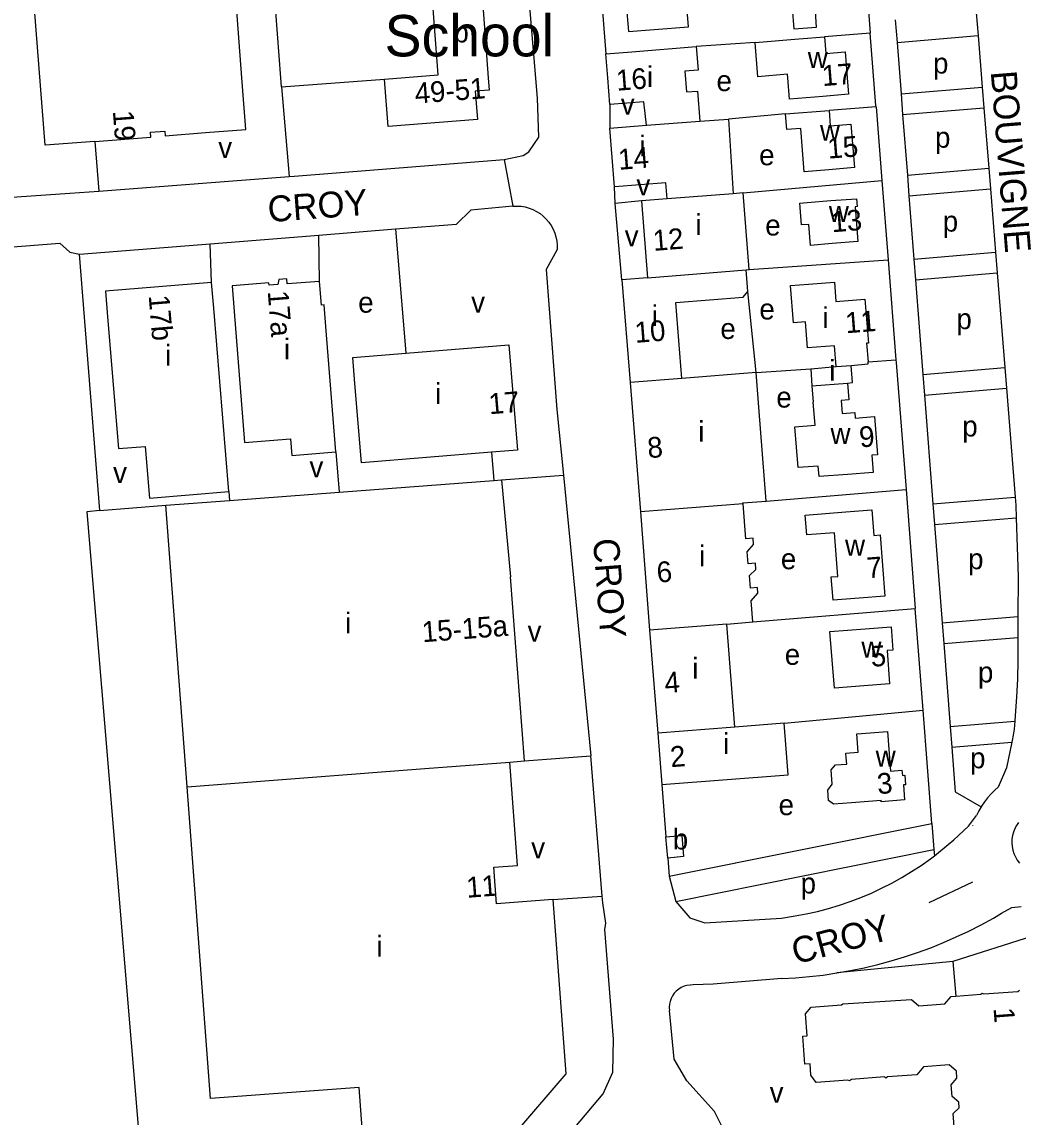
# Model space of a CAD drawing. Extents: x 157794 to 159375, y 380877 to 382306.
# Drawn here: x 158040.7 to 158233.2, y 381049.1 to 381260.8 of the extents above; entities that cross this region are included whole.
import ezdxf

# ---------------------------------------------------------------- set-up
doc = ezdxf.new("R2010")
doc.units = 0
for name, color, linetype in [('BLT_Basislijn', 7, 'Continuous'), ('BLT_Bebouwing', 7, 'Continuous'), ('BLT_Bebouwing_beschrifting', 7, 'Continuous'), ('BLT_Centroide', 7, 'Continuous'), ('BLT_Huisnummer', 7, 'Continuous'), ('BLT_Huisnummer_reeks', 7, 'Continuous'), ('BLT_Onderverdeling_panden', 7, 'Continuous'), ('BLT_Straatnaam', 7, 'Continuous'), ('BLT_Vlakafsluiter', 7, 'Continuous')]:
    doc.layers.add(name, color=color, linetype=linetype)

msp = doc.modelspace()

# ---------------------------------------------------------------- linework, layer by layer
at = {"layer": 'BLT_Basislijn'}
for p, q in [((158203.06, 381278.59), (158204.63, 381258.58)), ((158209.46, 381261.2), (158209.8, 381256.81)), ((158225.1, 381262.52), (158225.45, 381258.13)), ((158182.38, 381256.8), (158170.99, 381256.05)), ((158204.63, 381258.58), (158195.78, 381257.9)), ((158209.8, 381256.81), (158225.45, 381258.13)), ((158209.8, 381256.81), (158210.57, 381246.86)), ((158225.45, 381258.13), (158226.25, 381248.18)), ((158090.89, 381248.22), (158092.33, 381230.92)), ((158210.57, 381246.86), (158226.25, 381248.18)), ((158226.25, 381248.18), (158226.57, 381244.2)), ((158210.57, 381246.86), (158210.88, 381242.87)), ((158154.32, 381244.8), (158154.33, 381240.28)), ((158205.73, 381244.37), (158196.68, 381243.69)), ((158205.73, 381244.37), (158206.87, 381230.12)), ((158210.88, 381242.87), (158226.57, 381244.2)), ((158226.57, 381244.2), (158227.51, 381232.49)), ((158188.24, 381243.01), (158177.2, 381241.97)), ((158210.88, 381242.87), (158211.79, 381231.17)), ((158054.79, 381237.69), (158055.55, 381228.07)), ((158211.79, 381231.17), (158227.51, 381232.49)), ((158211.79, 381231.17), (158212.1, 381227.18)), ((158227.51, 381232.49), (158227.83, 381228.5)), ((158180.08, 381227.74), (158206.87, 381230.12)), ((158206.87, 381230.12), (158208.07, 381214.79)), ((158033.61, 381226.55), (158050, 381227.68)), ((158050, 381227.68), (158055.55, 381228.07)), ((158155.35, 381225.66), (158155.23, 381228.89)), ((158212.1, 381227.18), (158227.83, 381228.5)), ((158212.1, 381227.18), (158213.05, 381214.94)), ((158227.83, 381228.5), (158228.81, 381216.27)), ((158135.57, 381225.18), (158127.42, 381224.43)), ((158160.4, 381226.2), (158155.35, 381225.66)), ((158156.65, 381210.97), (158155.35, 381225.66)), ((158112.92, 381220.77), (158114.91, 381196.74)), ((158077.08, 381217.89), (158098.07, 381219.58)), ((158098.23, 381210.64), (158098.07, 381219.58)), ((158077.37, 381210.43), (158077.08, 381217.89)), ((158050, 381216.26), (158051.87, 381215.87)), ((158055.79, 381166.34), (158051.87, 381215.87)), ((158181.24, 381212.95), (158208.07, 381214.79)), ((158208.07, 381214.79), (158209.57, 381195.5)), ((158213.05, 381214.94), (158228.81, 381216.27)), ((158213.05, 381214.94), (158213.36, 381210.95)), ((158228.81, 381216.27), (158229.13, 381212.28)), ((158213.36, 381210.95), (158229.13, 381212.28)), ((158229.13, 381212.28), (158230.6, 381194)), ((158213.36, 381210.95), (158214.78, 381192.66)), ((158182.56, 381193.02), (158180.97, 381208.68)), ((158204.19, 381195.06), (158209.57, 381195.5)), ((158182.56, 381193.02), (158193.11, 381193.77)), ((158214.78, 381192.66), (158230.6, 381194)), ((158230.6, 381194), (158230.92, 381190.01)), ((158214.78, 381192.66), (158215.09, 381188.67)), ((158215.09, 381188.67), (158230.92, 381190.01)), ((158230.92, 381190.01), (158232.61, 381168.96)), ((158215.09, 381188.67), (158216.73, 381167.62)), ((158144.09, 381185.9), (158145.33, 381173.21)), ((158101.36, 381177.67), (158102.03, 381169.92)), ((158131.46, 381177.65), (158131.91, 381172.18)), ((158133.4, 381172.29), (158145.33, 381173.21)), ((158145.33, 381173.21), (158150.66, 381118.94)), ((158080.69, 381170), (158080.82, 381168.32)), ((158184.5, 381168.16), (158211.54, 381170.43)), ((158211.54, 381170.43), (158213.3, 381147.4)), ((158216.73, 381167.62), (158232.61, 381168.96)), ((158216.73, 381167.62), (158217.04, 381163.63)), ((158055.79, 381166.34), (158068.52, 381167.4)), ((158217.04, 381163.63), (158232.81, 381164.96)), ((158217.04, 381163.63), (158218.51, 381144.62)), ((158181.95, 381144.82), (158213.3, 381147.4)), ((158214.81, 381127.79), (158213.3, 381147.4)), ((158218.51, 381144.62), (158233.16, 381145.85)), ((158218.51, 381144.62), (158218.82, 381140.63)), ((158233.16, 381145.85), (158233.16, 381141.84)), ((158218.82, 381140.63), (158233.16, 381141.84)), ((158218.82, 381140.63), (158220.07, 381124.59)), ((158233.16, 381141.84), (158233.16, 381140.95)), ((158187.99, 381125.25), (158214.81, 381127.79)), ((158220.07, 381124.59), (158232.54, 381125.65)), ((158232.54, 381125.65), (158232.4, 381124.07)), ((158220.07, 381124.59), (158220.38, 381120.61)), ((158220.38, 381120.61), (158231.95, 381121.58)), ((158137.8, 381117.96), (158150.66, 381118.94)), ((158152.83, 381091.85), (158150.66, 381118.94)), ((158220.38, 381120.61), (158221.05, 381111.99)), ((158164.36, 381113.38), (158165.13, 381103.3)), ((158221.05, 381111.99), (158226.03, 381109.1)), ((158166.44, 381095.8), (158216.5, 381105.89)), ((158216.5, 381105.89), (158216.89, 381100.87)), ((158167.03, 381090.82), (158216.89, 381100.87)), ((158216.89, 381100.87), (158217, 381099.65)), ((158165.49, 381099.2), (158165.77, 381095.67)), ((158165.77, 381095.67), (158167.03, 381090.82)), ((158215.99, 381090.61), (158224.43, 381094.6)), ((158143.27, 381091.16), (158152.83, 381091.85)), ((158220.59, 381079.21), (158198.19, 381076.98))]:
    msp.add_line(p, q, dxfattribs=at)
for points in [[(158133.87, 381234.19), (158137.53, 381234.99), (158138.64, 381235.68), (158140.56, 381238.52), (158140.35, 381246.06), (158136.8, 381288.28), (158131.92, 381296.7)], [(158150.31, 381290.48), (158152, 381274.32), (158153.56, 381254.59)], [(158205.73, 381244.37), (158205.71, 381244.64), (158204.63, 381258.58)], [(158092.33, 381230.92), (158093.31, 381231), (158133.87, 381234.19)], [(158055.55, 381228.07), (158056.4, 381228.12), (158092.33, 381230.92)], [(158135.57, 381225.18), (158136.36, 381225.2), (158137.16, 381225.15), (158137.94, 381225.02), (158138.71, 381224.8), (158139.45, 381224.52), (158140.15, 381224.16), (158140.82, 381223.73), (158141.44, 381223.23), (158142.01, 381222.68), (158142.52, 381222.07), (158142.97, 381221.41), (158143.35, 381220.71), (158143.65, 381219.98), (158143.88, 381219.22), (158144.04, 381218.44), (158144.11, 381217.65), (158144.1, 381216.85), (158144.09, 381216.65)], [(158112.92, 381220.77), (158124.71, 381221.72), (158127.42, 381224.43)], [(158098.07, 381219.58), (158112.92, 381220.77)], [(158033.14, 381216.87), (158048.04, 381218.01), (158050, 381216.26)], [(158051.87, 381215.87), (158077.08, 381217.89)], [(158144.09, 381216.65), (158141.99, 381212.95), (158144.09, 381185.9)], [(158209.57, 381195.5), (158209.61, 381194.97), (158211.54, 381170.43)], [(158232.61, 381168.96), (158232.73, 381167.37), (158232.81, 381164.96)], [(158055.79, 381166.34), (158053.25, 381166.13), (158064.63, 381029.51)], [(158232.81, 381164.96), (158233.17, 381153.63), (158233.16, 381145.85)], [(158233.16, 381140.95), (158233.15, 381137.4), (158233.06, 381133.85), (158232.89, 381130.3), (158232.64, 381126.76), (158232.54, 381125.65)], [(158165.77, 381095.67), (158216.5, 381105.89), (158214.81, 381127.79)], [(158232.4, 381124.07), (158232.26, 381122.97), (158232.04, 381121.89), (158231.95, 381121.58)], [(158231.95, 381121.58), (158230.97, 381116.6), (158229.36, 381112.87), (158228.7, 381112.31), (158227.97, 381111.6), (158227.29, 381110.84), (158226.66, 381110.04), (158226.08, 381109.19), (158226.03, 381109.1)], [(158226.03, 381109.1), (158225.57, 381108.32), (158225.12, 381107.41)], [(158217, 381099.65), (158219.68, 381101.8), (158220.75, 381102.74), (158223.63, 381105.34), (158225.12, 381107.41)], [(158224.39, 381105.47), (158224.37, 381105.39)], [(158233.26, 381106.09), (158232.86, 381105.51), (158232.53, 381104.88), (158232.28, 381104.22), (158232.1, 381103.54), (158231.99, 381102.84), (158231.97, 381102.13), (158232.03, 381101.42), (158232.16, 381100.73), (158232.38, 381100.05), (158232.66, 381099.41), (158233.02, 381098.8), (158233.45, 381098.23)], [(158190.1, 381088.02), (158192.26, 381088.41), (158194.41, 381088.89), (158196.54, 381089.45), (158198.65, 381090.08), (158200.74, 381090.79), (158202.8, 381091.57), (158204.83, 381092.43), (158206.82, 381093.36), (158208.79, 381094.36), (158210.71, 381095.43), (158212.59, 381096.57), (158214.43, 381097.78), (158216.23, 381099.06), (158217, 381099.65)], [(158153.51, 381086.58), (158152.93, 381090.55), (158152.83, 381091.85)], [(158167.03, 381090.82), (158169.73, 381087.66), (158172.66, 381086.7), (158187.45, 381087.58), (158190.1, 381088.02)], [(158198.19, 381076.98), (158200.83, 381077.44), (158203.46, 381077.99), (158206.07, 381078.61), (158208.66, 381079.31), (158211.23, 381080.08), (158213.77, 381080.93), (158216.29, 381081.86), (158218.78, 381082.86), (158221.24, 381083.94), (158223.67, 381085.09), (158226.06, 381086.31), (158228.41, 381087.6), (158229.96, 381088.51), (158232, 381089.65), (158233.76, 381089.86)], [(158146.39, 381036.63), (158146.02, 381039.6), (158146.08, 381042.39), (158146.66, 381045.27), (158147.55, 381047.09), (158153.02, 381053.61), (158154.88, 381057.84), (158155.01, 381064.16), (158153.31, 381085.39), (158153.51, 381086.58)], [(158270.26, 381049.21), (158264.55, 381057.1), (158242.11, 381083.24), (158235.98, 381084.09), (158220.59, 381079.21)], [(158220.59, 381079.21), (158221.12, 381072.53)], [(158187.51, 381075.91), (158190.19, 381076.06), (158192.87, 381076.29), (158195.53, 381076.59), (158198.19, 381076.98)], [(158170.38, 381074.66), (158169.8, 381074.65), (158169.21, 381074.57), (158168.65, 381074.41), (158168.11, 381074.17), (158167.61, 381073.86), (158167.15, 381073.49), (158166.75, 381073.06), (158166.41, 381072.58), (158166.14, 381072.06), (158165.94, 381071.5), (158165.82, 381070.93), (158165.78, 381070.34), (158165.82, 381069.75)], [(158187.51, 381075.91), (158174.25, 381074.85), (158170.38, 381074.66)], [(158176.86, 381044.92), (158176.64, 381045.97), (158174.54, 381050.2), (158169.18, 381056.11), (158166.74, 381060.33), (158165.82, 381069.75)]]:
    msp.add_lwpolyline(points, dxfattribs=at)
at = {"layer": 'BLT_Bebouwing'}
for p, q in [((158090.89, 381248.22), (158110.77, 381249.75)), ((158171.71, 381241.62), (158177.2, 381241.97)), ((158154.33, 381240.28), (158161.4, 381240.84)), ((158155.23, 381228.89), (158154.33, 381240.28)), ((158180.08, 381227.74), (158178.12, 381227.59)), ((158181.24, 381212.95), (158180.08, 381227.74)), ((158165.39, 381226.59), (158160.4, 381226.2)), ((158160.4, 381226.2), (158161.57, 381211.35)), ((158180.64, 381212.9), (158181.24, 381212.95)), ((158161.57, 381211.35), (158156.65, 381210.97)), ((158156.65, 381210.97), (158158.23, 381191.11)), ((158168.21, 381191.89), (158167.06, 381206.57)), ((158182.56, 381193.02), (158168.21, 381191.89)), ((158183.08, 381186.34), (158182.56, 381193.02)), ((158193.11, 381193.77), (158193.35, 381190.44)), ((158158.23, 381191.11), (158160.2, 381166.09)), ((158184.5, 381168.16), (158183.08, 381186.34)), ((158080.82, 381168.32), (158102.03, 381169.92)), ((158068.52, 381167.4), (158080.82, 381168.32)), ((158072.63, 381112.93), (158068.52, 381167.4)), ((158160.2, 381166.09), (158162, 381143.26)), ((158137.8, 381117.96), (158135.11, 381153.57)), ((158176.89, 381144.42), (158181.95, 381144.82)), ((158178.45, 381124.5), (158176.89, 381144.42)), ((158162, 381143.26), (158163.57, 381123.34)), ((158163.57, 381123.34), (158164.36, 381113.38)), ((158187.99, 381125.25), (158178.45, 381124.5)), ((158134.96, 381117.74), (158137.8, 381117.96)), ((158077.17, 381052.71), (158072.63, 381112.93)), ((158165.49, 381099.2), (158165.13, 381103.3))]:
    msp.add_line(p, q, dxfattribs=at)
for points in [[(158054.79, 381237.69), (158045.23, 381236.94), (158041.07, 381289.74)], [(158156.59, 381274.84), (158157.91, 381258.9), (158162.9, 381259.31), (158169.5, 381259.86), (158168.19, 381275.76)], [(158193.96, 381263.82), (158198.95, 381264.21), (158198.29, 381272.67), (158191.92, 381272.17), (158191.61, 381276.08), (158186.63, 381275.69), (158182.05, 381275.34), (158182.4, 381270.84), (158184.74, 381271.02), (158185.05, 381267.03), (158189.21, 381267.36), (158189.51, 381263.47), (158189.83, 381259.42), (158194.22, 381259.76), (158193.96, 381263.82)], [(158076.2, 381239.39), (158083.99, 381239.99), (158083.23, 381250), (158081.63, 381270.7)], [(158090.89, 381248.22), (158090.76, 381250), (158089.11, 381271.27)], [(158119.84, 381267.68), (158129.43, 381268.39), (158130.79, 381250), (158130.97, 381247.6), (158128.29, 381247.4), (158128.71, 381241.9), (158111.47, 381240.57), (158110.77, 381249.75)], [(158182.38, 381256.8), (158190.8, 381257.49), (158195.78, 381257.9)], [(158195.78, 381257.9), (158196.04, 381254.68), (158199.77, 381254.99), (158200.18, 381250), (158200.44, 381246.81), (158195.46, 381246.4), (158189.03, 381245.87), (158188.69, 381250), (158188.64, 381250.66), (158182.92, 381250.19), (158182.38, 381256.8)], [(158153.56, 381254.59), (158158.54, 381254.98), (158170.99, 381256.05)], [(158154.32, 381244.8), (158153.92, 381250), (158153.56, 381254.59)], [(158170.99, 381256.05), (158171.35, 381251.47), (158168.81, 381251.27), (158169.13, 381247.27), (158171.26, 381247.41), (158171.71, 381241.62)], [(158161.4, 381240.84), (158160.9, 381245.32), (158154.32, 381244.8)], [(158177.2, 381241.97), (158178.12, 381227.59)], [(158188.24, 381243.01), (158196.68, 381243.69)], [(158196.59, 381232.21), (158191.88, 381231.82), (158191.19, 381240.19), (158188.49, 381239.97), (158188.24, 381243.01)], [(158196.68, 381243.69), (158196.9, 381240.68), (158200.88, 381241), (158201.57, 381232.62), (158196.59, 381232.21)], [(158054.79, 381237.69), (158065.62, 381238.53), (158065.55, 381239.45), (158068.34, 381239.67), (158068.4, 381238.79), (158076.2, 381239.39)], [(158165.39, 381226.59), (158165.15, 381229.67), (158155.23, 381228.89)], [(158197.24, 381217.93), (158193.07, 381217.6), (158192.76, 381221.65), (158191.36, 381221.54), (158191.03, 381225.77), (158192.43, 381225.88), (158196.97, 381226.24), (158201.96, 381226.62), (158202.08, 381225.1), (158201.7, 381225.07), (158202.23, 381218.32), (158197.24, 381217.93)], [(158180.97, 381208.68), (158180.64, 381212.9)], [(158077.37, 381210.43), (158056.87, 381208.75), (158057.27, 381203.77), (158059.36, 381178.33), (158064.56, 381178.75), (158065.38, 381168.75), (158080.69, 381170)], [(158080.69, 381170), (158077.78, 381205.45), (158077.37, 381210.43)], [(158098.23, 381210.64), (158091.95, 381210.14), (158091.87, 381211.1), (158090.36, 381210.98), (158090.18, 381210.04), (158088.48, 381209.9), (158088.44, 381210.38), (158081.33, 381209.81), (158081.73, 381204.83), (158083.75, 381179.47), (158092.61, 381180.18), (158092.86, 381176.99), (158101.36, 381177.67)], [(158101.36, 381177.67), (158099.49, 381201.1), (158099.1, 381206.09), (158098.6, 381206.05), (158098.23, 381210.64)], [(158198.04, 381194.17), (158197.73, 381198.21), (158192.48, 381197.8), (158192.09, 381202.83), (158189.77, 381202.65), (158189.21, 381209.83), (158192.7, 381210.1), (158197.69, 381210.49), (158197.98, 381206.77), (158203.58, 381207.21), (158204.25, 381198.72), (158203.91, 381198.7), (158204.19, 381195.06)], [(158167.06, 381206.57), (158180.05, 381207.6), (158180.97, 381208.68)], [(158114.91, 381196.74), (158134.78, 381198.37), (158136.45, 381178.05), (158131.46, 381177.65)], [(158131.46, 381177.65), (158106.33, 381175.59), (158105.07, 381190.92), (158104.66, 381195.9), (158114.91, 381196.74)], [(158200.25, 381191), (158201.2, 381191.09), (158200.93, 381194.41)], [(158200.93, 381194.41), (158204.22, 381194.73), (158204.19, 381195.06)], [(158200.25, 381191), (158200.51, 381187.73), (158199.01, 381187.59), (158199.22, 381185.11), (158201.61, 381185.32), (158201.69, 381184.23), (158205.43, 381184.52)], [(158193.35, 381190.44), (158193.59, 381187.27)], [(158205.43, 381184.52), (158206.01, 381177.11), (158204.95, 381177.03), (158205.21, 381173.72), (158200.23, 381173.33), (158194.74, 381172.9), (158194.58, 381174.96), (158190.66, 381174.66), (158190.05, 381182.53), (158193.96, 381182.84), (158193.59, 381187.27)], [(158102.03, 381169.92), (158131.91, 381172.18)], [(158131.91, 381172.18), (158133.4, 381172.29)], [(158133.4, 381172.29), (158135.11, 381153.57)], [(158180.04, 381167.67), (158180.03, 381167.81), (158184.5, 381168.16)], [(158181.95, 381144.82), (158181.63, 381148.93), (158182.9, 381150.41), (158182.82, 381151.49), (158181.45, 381151.38), (158181.26, 381153.82), (158182.51, 381154.98), (158182.42, 381156.18), (158181.03, 381156.07), (158180.86, 381158.36), (158182.08, 381159.8), (158181.99, 381160.99), (158180.58, 381160.88), (158180.04, 381167.67)], [(158202.47, 381149.4), (158197.45, 381149.01), (158197.09, 381153.54), (158198.33, 381153.63), (158197.68, 381162.05), (158192.34, 381161.63), (158192.04, 381165.49), (158199.91, 381166.1), (158204.9, 381166.49), (158205.28, 381161.56), (158206.52, 381161.66), (158207.45, 381149.79), (158202.47, 381149.4)], [(158203.65, 381143.5), (158208.64, 381143.89), (158208.99, 381139.38), (158207.86, 381139.3), (158208.36, 381132.84), (158203.38, 381132.45), (158197.68, 381132), (158196.83, 381142.97), (158203.65, 381143.5)], [(158164.36, 381113.38), (158188.76, 381115.29), (158188.37, 381120.27), (158187.99, 381125.25)], [(158202.94, 381123.26), (158207.93, 381123.65), (158208.52, 381116), (158210.74, 381116.18), (158210.82, 381115.14), (158211.3, 381115.18), (158211.44, 381113.37), (158211.01, 381113.34), (158211.24, 381110.42), (158206.72, 381110.07), (158206.7, 381110.32), (158201, 381109.88), (158197.52, 381109.6), (158196.58, 381110.31), (158196.42, 381112.34), (158197.28, 381113.48), (158197.06, 381116.26), (158197.9, 381117.18), (158200.07, 381117.35), (158199.97, 381118.54), (158199.9, 381119.45), (158202.3, 381119.64), (158202.02, 381123.19), (158202.94, 381123.26)], [(158143.27, 381091.16), (158132.4, 381090.34), (158131.87, 381097.4), (158136.46, 381097.75), (158134.96, 381117.74)], [(158165.13, 381103.3), (158168.2, 381103.58), (158168.55, 381099.47), (158165.49, 381099.2)], [(158143.27, 381091.16), (158145.81, 381057.52), (158136.44, 381046.62), (158131.46, 381046.24), (158106.65, 381044.38), (158105.86, 381054.88), (158077.17, 381052.71)], [(158193.22, 381070.36), (158199.06, 381070.8), (158199.35, 381071), (158212.61, 381071.85), (158214.01, 381070.65), (158219.04, 381071.03), (158220.28, 381072.46), (158221.12, 381072.53)], [(158221.12, 381072.53), (158226.01, 381072.9), (158226.27, 381073.07), (158226.58, 381072.92), (158233.15, 381073.42), (158233.48, 381073.65)], [(158221.11, 381043.83), (158220.66, 381049.81), (158221.82, 381050.89), (158221.73, 381052), (158220.45, 381053.1), (158220.28, 381055.37), (158221.37, 381056.65), (158221.27, 381058.02), (158219.87, 381059.22), (158214.93, 381058.85), (158213.62, 381057.32), (158207.98, 381056.9), (158207.64, 381056.67), (158207.4, 381056.88), (158200.98, 381056.39), (158200.58, 381056.11), (158200.28, 381056.26), (158194.15, 381055.8), (158193.16, 381057.25), (158192.99, 381059.43), (158191.99, 381059.35), (158191.58, 381064.77), (158192.44, 381064.84), (158192.12, 381069.08), (158193.22, 381070.36)]]:
    msp.add_lwpolyline(points, dxfattribs=at)
at = {"layer": 'BLT_Onderverdeling_panden'}
for p, q in [((158161.4, 381240.84), (158171.71, 381241.62)), ((158178.12, 381227.59), (158165.39, 381226.59)), ((158161.57, 381211.35), (158180.64, 381212.9)), ((158198.04, 381194.17), (158200.93, 381194.41)), ((158168.21, 381191.89), (158158.23, 381191.11)), ((158180.04, 381167.67), (158160.2, 381166.09)), ((158176.89, 381144.42), (158162, 381143.26)), ((158178.45, 381124.5), (158163.57, 381123.34)), ((158118.57, 381116.48), (158134.96, 381117.74)), ((158072.63, 381112.93), (158118.57, 381116.48))]:
    msp.add_line(p, q, dxfattribs=at)
for points in [[(158110.77, 381249.75), (158121.11, 381250.55), (158119.84, 381267.68)], [(158193.11, 381193.77), (158198.04, 381194.17)], [(158193.35, 381190.44), (158200.25, 381191)]]:
    msp.add_lwpolyline(points, dxfattribs=at)
at = {"layer": 'BLT_Vlakafsluiter'}
msp.add_line((158133.87, 381234.19), (158135.57, 381225.18), dxfattribs=at)

# ---------------------------------------------------------------- texts
at = {"layer": 'BLT_Bebouwing_beschrifting'}
msp.add_text('School', height=8, dxfattribs=at).set_placement((158110.79, 381254.12))
at = {"layer": 'BLT_Centroide'}
for s, p in [('b', (158124.09, 381256.81)), ('w', (158192.55, 381251.88)), ('i', (158161.48, 381248.19)), ('p', (158216.75, 381250.8)), ('e', (158174.91, 381247.41)), ('v', (158156.43, 381242.89)), ('w', (158194.91, 381237.81)), ('p', (158217.13, 381236.47)), ('v', (158078.65, 381234.5)), ('i', (158160.02, 381234.8)), ('e', (158183.15, 381233.08)), ('v', (158159.45, 381227.28)), ('w', (158196.62, 381222.12)), ('i', (158170.82, 381219.62)), ('p', (158218.63, 381220.26)), ('e', (158184.33, 381219.5)), ('v', (158157.19, 381217.44)), ('e', (158105.69, 381204.59)), ('v', (158127.52, 381204.59)), ('i', (158162.4, 381202)), ('e', (158183.2, 381203.28)), ('i', (158195.36, 381201.62)), ('p', (158221.27, 381201.4)), ('e', (158175.66, 381199.51)), ('i', (158091.34, 381195.56)), ('i', (158068.36, 381194.38)), ('i', (158196.7, 381191.44)), ('i', (158120.55, 381186.97)), ('e', (158186.47, 381186.25)), ('i', (158171.38, 381179.64)), ('p', (158222.4, 381180.66)), ('w', (158196.94, 381179.23)), ('v', (158058.34, 381171.67)), ('v', (158096.28, 381172.78)), ('i', (158171.55, 381155.58)), ('w', (158199.75, 381157.64)), ('e', (158187.35, 381155.01)), ('p', (158223.53, 381155.01)), ('i', (158103.16, 381142.62)), ('v', (158138.42, 381141.04)), ('w', (158202.91, 381137.92)), ('i', (158170.23, 381133.88)), ('e', (158188.1, 381136.53)), ('p', (158225.42, 381133.13)), ('i', (158176.17, 381119.31)), ('w', (158205.67, 381116.86)), ('p', (158223.91, 381116.54)), ('e', (158186.91, 381107.48)), ('b', (158166.47, 381100.85)), ('v', (158139.12, 381099.14)), ('p', (158191.17, 381092.34)), ('i', (158109.22, 381080.16)), ('v', (158185.19, 381051.89))]:
    msp.add_text(s, height=4, dxfattribs=at).set_placement(p)
at = {"layer": 'BLT_Huisnummer'}
for s, rotation, p in [('17', 4.4709, (158195.43, 381248.37)), ('16', 4.4729, (158155.66, 381247.47)), ('19', 274.3866, (158058.28, 381243.55)), ('15', 4.4709, (158196.49, 381234.35)), ('14', 4.4729, (158156.05, 381232.19)), ('13', 4.4709, (158197.24, 381220.12)), ('12', 4.4729, (158162.75, 381216.52)), ('17a', 274.5633, (158088.2, 381208.72)), ('17b', 274.6857, (158065.2, 381207.9)), ('11', 4.4709, (158199.94, 381200.6)), ('10', 4.4729, (158159.25, 381198.75)), ('17', 4.6869, (158131.05, 381184.95)), ('9', 4.4709, (158202.63, 381178.54)), ('8', 4.4729, (158161.71, 381176.47)), ('7', 4.4709, (158204.07, 381153.26)), ('6', 4.4729, (158163.5, 381152.41)), ('5', 4.4709, (158204.84, 381136.14)), ('4', 4.4729, (158165, 381131.05)), ('2', 4.4745, (158166.1, 381116.74)), ('3', 4.4709, (158206.08, 381111.53)), ('11', 4.314, (158126.72, 381091.5)), ('1', 274.318, (158228.43, 381070.17))]:
    msp.add_text(s, height=4, rotation=rotation, dxfattribs=at).set_placement(p)
at = {"layer": 'BLT_Huisnummer_reeks'}
for s, rotation, p in [('49-51', 4.4081, (158116.76, 381244.99)), ('15-15a', 4.4177, (158118.13, 381140.89))]:
    msp.add_text(s, height=4, rotation=rotation, dxfattribs=at).set_placement(p)
at = {"layer": 'BLT_Straatnaam'}
for s, rotation, p in [('BOUVIGNE', 274.5867, (158227.89, 381251.18)), ('CROY', 4.309, (158088.39, 381222.07)), ('CROY', 274.309, (158151.05, 381160.82)), ('CROY', 14.7581, (158190.2, 381078.62))]:
    msp.add_text(s, height=5, rotation=rotation, dxfattribs=at).set_placement(p)

doc.saveas('drawing.dxf')
